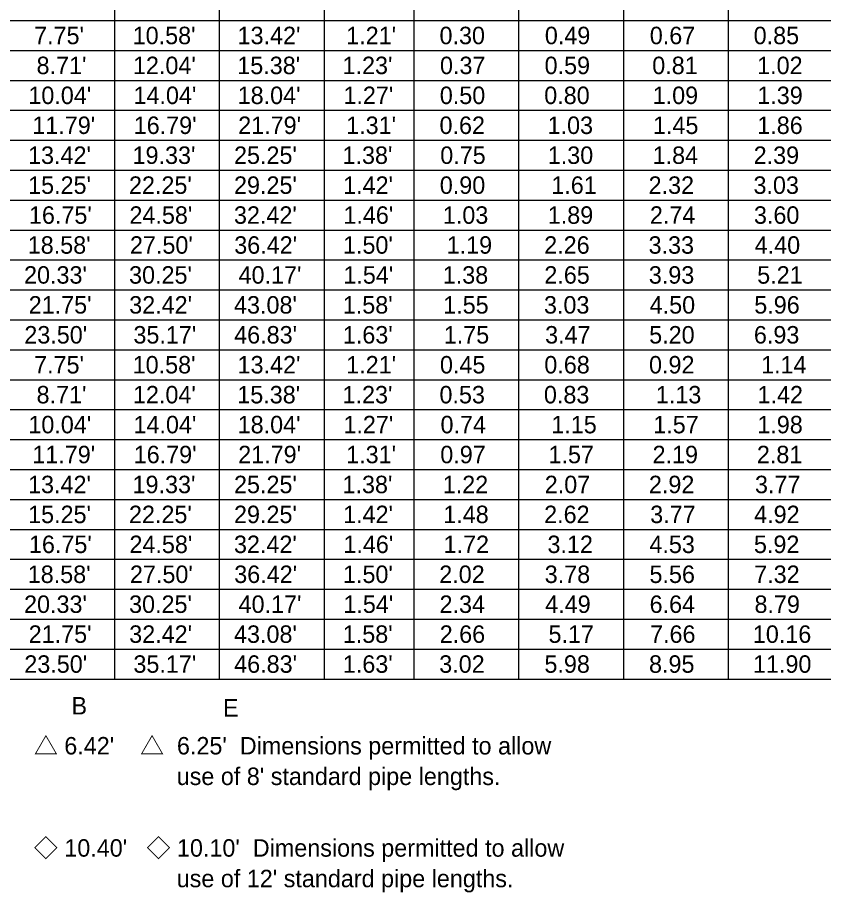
# Model space of a CAD drawing. Extents: x -1.3 to 14.6, y 0 to 8.4.
# Drawn here: x 6.831 to 10.062, y 1.334 to 4.842 of the extents above; entities that cross this region are included whole.
import ezdxf

# ---------------------------------------------------------------- set-up
doc = ezdxf.new("R2010")
doc.units = 0
doc.layers.add('Table', color=7, linetype='Continuous')

msp = doc.modelspace()

# ---------------------------------------------------------------- linework, layer by layer
at = {"layer": 'Table'}
for points in [[(7.22, 4.95), (7.22, 4.83), (7.22, 4.71), (7.22, 4.59), (7.22, 4.47), (7.22, 4.35), (7.22, 4.23), (7.22, 4.11), (7.22, 3.99), (7.22, 3.87), (7.22, 3.75), (7.22, 3.63), (7.22, 3.51), (7.22, 3.39), (7.22, 3.27), (7.22, 3.15), (7.22, 3.03), (7.22, 2.91), (7.22, 2.79), (7.22, 2.67), (7.22, 2.55), (7.22, 2.43), (7.22, 2.31), (7.22, 2.19)], [(7.64, 4.95), (7.64, 4.83), (7.64, 4.71), (7.64, 4.59), (7.64, 4.47), (7.64, 4.35), (7.64, 4.23), (7.64, 4.11), (7.64, 3.99), (7.64, 3.87), (7.64, 3.75), (7.64, 3.63), (7.64, 3.51), (7.64, 3.39), (7.64, 3.27), (7.64, 3.15), (7.64, 3.03), (7.64, 2.91), (7.64, 2.79), (7.64, 2.67), (7.64, 2.55), (7.64, 2.43), (7.64, 2.31), (7.64, 2.19)], [(8.06, 4.95), (8.06, 4.83), (8.06, 4.71), (8.06, 4.59), (8.06, 4.47), (8.06, 4.35), (8.06, 4.23), (8.06, 4.11), (8.06, 3.99), (8.06, 3.87), (8.06, 3.75), (8.06, 3.63), (8.06, 3.51), (8.06, 3.39), (8.06, 3.27), (8.06, 3.15), (8.06, 3.03), (8.06, 2.91), (8.06, 2.79), (8.06, 2.67), (8.06, 2.55), (8.06, 2.43), (8.06, 2.31), (8.06, 2.19)], [(8.42, 4.95), (8.42, 4.83), (8.42, 4.71), (8.42, 4.59), (8.42, 4.47), (8.42, 4.35), (8.42, 4.23), (8.42, 4.11), (8.42, 3.99), (8.42, 3.87), (8.42, 3.75), (8.42, 3.63), (8.42, 3.51), (8.42, 3.39), (8.42, 3.27), (8.42, 3.15), (8.42, 3.03), (8.42, 2.91), (8.42, 2.79), (8.42, 2.67), (8.42, 2.55), (8.42, 2.43), (8.42, 2.31), (8.42, 2.19)], [(8.84, 4.95), (8.84, 4.83), (8.84, 4.71), (8.84, 4.59), (8.84, 4.47), (8.84, 4.35), (8.84, 4.23), (8.84, 4.11), (8.84, 3.99), (8.84, 3.87), (8.84, 3.75), (8.84, 3.63), (8.84, 3.51), (8.84, 3.39), (8.84, 3.27), (8.84, 3.15), (8.84, 3.03), (8.84, 2.91), (8.84, 2.79), (8.84, 2.67), (8.84, 2.55), (8.84, 2.43), (8.84, 2.31), (8.84, 2.19)], [(9.26, 4.95), (9.26, 4.83), (9.26, 4.71), (9.26, 4.59), (9.26, 4.47), (9.26, 4.35), (9.26, 4.23), (9.26, 4.11), (9.26, 3.99), (9.26, 3.87), (9.26, 3.75), (9.26, 3.63), (9.26, 3.51), (9.26, 3.39), (9.26, 3.27), (9.26, 3.15), (9.26, 3.03), (9.26, 2.91), (9.26, 2.79), (9.26, 2.67), (9.26, 2.55), (9.26, 2.43), (9.26, 2.31), (9.26, 2.19)], [(9.68, 4.95), (9.68, 4.83), (9.68, 4.71), (9.68, 4.59), (9.68, 4.47), (9.68, 4.35), (9.68, 4.23), (9.68, 4.11), (9.68, 3.99), (9.68, 3.87), (9.68, 3.75), (9.68, 3.63), (9.68, 3.51), (9.68, 3.39), (9.68, 3.27), (9.68, 3.15), (9.68, 3.03), (9.68, 2.91), (9.68, 2.79), (9.68, 2.67), (9.68, 2.55), (9.68, 2.43), (9.68, 2.31), (9.68, 2.19)], [(4.04, 4.83), (4.52, 4.83), (4.94, 4.83), (5.42, 4.83), (5.66, 4.83), (6.02, 4.83), (6.38, 4.83), (6.8, 4.83), (7.22, 4.83), (7.64, 4.83), (8.06, 4.83), (8.42, 4.83), (8.84, 4.83), (9.26, 4.83), (9.68, 4.83), (10.1, 4.83), (10.52, 4.83), (10.94, 4.83), (11.36, 4.83), (11.78, 4.83), (12.2, 4.83), (12.62, 4.83), (13.04, 4.83), (13.46, 4.83)], [(4.04, 4.71), (4.52, 4.71), (4.94, 4.71), (5.42, 4.71), (5.66, 4.71), (6.02, 4.71), (6.38, 4.71), (6.8, 4.71), (7.22, 4.71), (7.64, 4.71), (8.06, 4.71), (8.42, 4.71), (8.84, 4.71), (9.26, 4.71), (9.68, 4.71), (10.1, 4.71), (10.52, 4.71), (10.94, 4.71), (11.36, 4.71), (11.78, 4.71), (12.2, 4.71), (12.62, 4.71), (13.04, 4.71), (13.46, 4.71)], [(4.04, 4.59), (4.52, 4.59), (4.94, 4.59), (5.42, 4.59), (5.66, 4.59), (6.02, 4.59), (6.38, 4.59), (6.8, 4.59), (7.22, 4.59), (7.64, 4.59), (8.06, 4.59), (8.42, 4.59), (8.84, 4.59), (9.26, 4.59), (9.68, 4.59), (10.1, 4.59), (10.52, 4.59), (10.94, 4.59), (11.36, 4.59), (11.78, 4.59), (12.2, 4.59), (12.62, 4.59), (13.04, 4.59), (13.46, 4.59)], [(4.04, 4.47), (4.52, 4.47), (4.94, 4.47), (5.42, 4.47), (5.66, 4.47), (6.02, 4.47), (6.38, 4.47), (6.8, 4.47), (7.22, 4.47), (7.64, 4.47), (8.06, 4.47), (8.42, 4.47), (8.84, 4.47), (9.26, 4.47), (9.68, 4.47), (10.1, 4.47), (10.52, 4.47), (10.94, 4.47), (11.36, 4.47), (11.78, 4.47), (12.2, 4.47), (12.62, 4.47), (13.04, 4.47), (13.46, 4.47)], [(4.04, 4.35), (4.52, 4.35), (4.94, 4.35), (5.42, 4.35), (5.66, 4.35), (6.02, 4.35), (6.38, 4.35), (6.8, 4.35), (7.22, 4.35), (7.64, 4.35), (8.06, 4.35), (8.42, 4.35), (8.84, 4.35), (9.26, 4.35), (9.68, 4.35), (10.1, 4.35), (10.52, 4.35), (10.94, 4.35), (11.36, 4.35), (11.78, 4.35), (12.2, 4.35), (12.62, 4.35), (13.04, 4.35), (13.46, 4.35)], [(4.04, 4.23), (4.52, 4.23), (4.94, 4.23), (5.42, 4.23), (5.66, 4.23), (6.02, 4.23), (6.38, 4.23), (6.8, 4.23), (7.22, 4.23), (7.64, 4.23), (8.06, 4.23), (8.42, 4.23), (8.84, 4.23), (9.26, 4.23), (9.68, 4.23), (10.1, 4.23), (10.52, 4.23), (10.94, 4.23), (11.36, 4.23), (11.78, 4.23), (12.2, 4.23), (12.62, 4.23), (13.04, 4.23), (13.46, 4.23)], [(4.04, 4.11), (4.52, 4.11), (4.94, 4.11), (5.42, 4.11), (5.66, 4.11), (6.02, 4.11), (6.38, 4.11), (6.8, 4.11), (7.22, 4.11), (7.64, 4.11), (8.06, 4.11), (8.42, 4.11), (8.84, 4.11), (9.26, 4.11), (9.68, 4.11), (10.1, 4.11), (10.52, 4.11), (10.94, 4.11), (11.36, 4.11), (11.78, 4.11), (12.2, 4.11), (12.62, 4.11), (13.04, 4.11), (13.46, 4.11)], [(4.04, 3.99), (4.52, 3.99), (4.94, 3.99), (5.42, 3.99), (5.66, 3.99), (6.02, 3.99), (6.38, 3.99), (6.8, 3.99), (7.22, 3.99), (7.64, 3.99), (8.06, 3.99), (8.42, 3.99), (8.84, 3.99), (9.26, 3.99), (9.68, 3.99), (10.1, 3.99), (10.52, 3.99), (10.94, 3.99), (11.36, 3.99), (11.78, 3.99), (12.2, 3.99), (12.62, 3.99), (13.04, 3.99), (13.46, 3.99)], [(4.04, 3.87), (4.52, 3.87), (4.94, 3.87), (5.42, 3.87), (5.66, 3.87), (6.02, 3.87), (6.38, 3.87), (6.8, 3.87), (7.22, 3.87), (7.64, 3.87), (8.06, 3.87), (8.42, 3.87), (8.84, 3.87), (9.26, 3.87), (9.68, 3.87), (10.1, 3.87), (10.52, 3.87), (10.94, 3.87), (11.36, 3.87), (11.78, 3.87), (12.2, 3.87), (12.62, 3.87), (13.04, 3.87), (13.46, 3.87)], [(4.04, 3.75), (4.52, 3.75), (4.94, 3.75), (5.42, 3.75), (5.66, 3.75), (6.02, 3.75), (6.38, 3.75), (6.8, 3.75), (7.22, 3.75), (7.64, 3.75), (8.06, 3.75), (8.42, 3.75), (8.84, 3.75), (9.26, 3.75), (9.68, 3.75), (10.1, 3.75), (10.52, 3.75), (10.94, 3.75), (11.36, 3.75), (11.78, 3.75), (12.2, 3.75), (12.62, 3.75), (13.04, 3.75), (13.46, 3.75)], [(4.04, 3.63), (4.52, 3.63), (4.94, 3.63), (5.42, 3.63), (5.66, 3.63), (6.02, 3.63), (6.38, 3.63), (6.8, 3.63), (7.22, 3.63), (7.64, 3.63), (8.06, 3.63), (8.42, 3.63), (8.84, 3.63), (9.26, 3.63), (9.68, 3.63), (10.1, 3.63), (10.52, 3.63), (10.94, 3.63), (11.36, 3.63), (11.78, 3.63), (12.2, 3.63), (12.62, 3.63), (13.04, 3.63), (13.46, 3.63)], [(4.04, 3.51), (4.52, 3.51), (4.94, 3.51), (5.42, 3.51), (5.66, 3.51), (6.02, 3.51), (6.38, 3.51), (6.8, 3.51), (7.22, 3.51), (7.64, 3.51), (8.06, 3.51), (8.42, 3.51), (8.84, 3.51), (9.26, 3.51), (9.68, 3.51), (10.1, 3.51), (10.52, 3.51), (10.94, 3.51), (11.36, 3.51), (11.78, 3.51), (12.2, 3.51), (12.62, 3.51), (13.04, 3.51), (13.46, 3.51)], [(4.04, 3.39), (4.52, 3.39), (4.94, 3.39), (5.42, 3.39), (5.66, 3.39), (6.02, 3.39), (6.38, 3.39), (6.8, 3.39), (7.22, 3.39), (7.64, 3.39), (8.06, 3.39), (8.42, 3.39), (8.84, 3.39), (9.26, 3.39), (9.68, 3.39), (10.1, 3.39), (10.52, 3.39), (10.94, 3.39), (11.36, 3.39), (11.78, 3.39), (12.2, 3.39), (12.62, 3.39), (13.04, 3.39), (13.46, 3.39)], [(4.04, 3.27), (4.52, 3.27), (4.94, 3.27), (5.42, 3.27), (5.66, 3.27), (6.02, 3.27), (6.38, 3.27), (6.8, 3.27), (7.22, 3.27), (7.64, 3.27), (8.06, 3.27), (8.42, 3.27), (8.84, 3.27), (9.26, 3.27), (9.68, 3.27), (10.1, 3.27), (10.52, 3.27), (10.94, 3.27), (11.36, 3.27), (11.78, 3.27), (12.2, 3.27), (12.62, 3.27), (13.04, 3.27), (13.46, 3.27)], [(4.04, 3.15), (4.52, 3.15), (4.94, 3.15), (5.42, 3.15), (5.66, 3.15), (6.02, 3.15), (6.38, 3.15), (6.8, 3.15), (7.22, 3.15), (7.64, 3.15), (8.06, 3.15), (8.42, 3.15), (8.84, 3.15), (9.26, 3.15), (9.68, 3.15), (10.1, 3.15), (10.52, 3.15), (10.94, 3.15), (11.36, 3.15), (11.78, 3.15), (12.2, 3.15), (12.62, 3.15), (13.04, 3.15), (13.46, 3.15)], [(4.04, 3.03), (4.52, 3.03), (4.94, 3.03), (5.42, 3.03), (5.66, 3.03), (6.02, 3.03), (6.38, 3.03), (6.8, 3.03), (7.22, 3.03), (7.64, 3.03), (8.06, 3.03), (8.42, 3.03), (8.84, 3.03), (9.26, 3.03), (9.68, 3.03), (10.1, 3.03), (10.52, 3.03), (10.94, 3.03), (11.36, 3.03), (11.78, 3.03), (12.2, 3.03), (12.62, 3.03), (13.04, 3.03), (13.46, 3.03)], [(4.04, 2.91), (4.52, 2.91), (4.94, 2.91), (5.42, 2.91), (5.66, 2.91), (6.02, 2.91), (6.38, 2.91), (6.8, 2.91), (7.22, 2.91), (7.64, 2.91), (8.06, 2.91), (8.42, 2.91), (8.84, 2.91), (9.26, 2.91), (9.68, 2.91), (10.1, 2.91), (10.52, 2.91), (10.94, 2.91), (11.36, 2.91), (11.78, 2.91), (12.2, 2.91), (12.62, 2.91), (13.04, 2.91), (13.46, 2.91)], [(4.04, 2.79), (4.52, 2.79), (4.94, 2.79), (5.42, 2.79), (5.66, 2.79), (6.02, 2.79), (6.38, 2.79), (6.8, 2.79), (7.22, 2.79), (7.64, 2.79), (8.06, 2.79), (8.42, 2.79), (8.84, 2.79), (9.26, 2.79), (9.68, 2.79), (10.1, 2.79), (10.52, 2.79), (10.94, 2.79), (11.36, 2.79), (11.78, 2.79), (12.2, 2.79), (12.62, 2.79), (13.04, 2.79), (13.46, 2.79)], [(4.04, 2.67), (4.52, 2.67), (4.94, 2.67), (5.42, 2.67), (5.66, 2.67), (6.02, 2.67), (6.38, 2.67), (6.8, 2.67), (7.22, 2.67), (7.64, 2.67), (8.06, 2.67), (8.42, 2.67), (8.84, 2.67), (9.26, 2.67), (9.68, 2.67), (10.1, 2.67), (10.52, 2.67), (10.94, 2.67), (11.36, 2.67), (11.78, 2.67), (12.2, 2.67), (12.62, 2.67), (13.04, 2.67), (13.46, 2.67)], [(4.04, 2.55), (4.52, 2.55), (4.94, 2.55), (5.42, 2.55), (5.66, 2.55), (6.02, 2.55), (6.38, 2.55), (6.8, 2.55), (7.22, 2.55), (7.64, 2.55), (8.06, 2.55), (8.42, 2.55), (8.84, 2.55), (9.26, 2.55), (9.68, 2.55), (10.1, 2.55), (10.52, 2.55), (10.94, 2.55), (11.36, 2.55), (11.78, 2.55), (12.2, 2.55), (12.62, 2.55), (13.04, 2.55), (13.46, 2.55)], [(4.04, 2.43), (4.52, 2.43), (4.94, 2.43), (5.42, 2.43), (5.66, 2.43), (6.02, 2.43), (6.38, 2.43), (6.8, 2.43), (7.22, 2.43), (7.64, 2.43), (8.06, 2.43), (8.42, 2.43), (8.84, 2.43), (9.26, 2.43), (9.68, 2.43), (10.1, 2.43), (10.52, 2.43), (10.94, 2.43), (11.36, 2.43), (11.78, 2.43), (12.2, 2.43), (12.62, 2.43), (13.04, 2.43), (13.46, 2.43)], [(4.04, 2.31), (4.52, 2.31), (4.94, 2.31), (5.42, 2.31), (5.66, 2.31), (6.02, 2.31), (6.38, 2.31), (6.8, 2.31), (7.22, 2.31), (7.64, 2.31), (8.06, 2.31), (8.42, 2.31), (8.84, 2.31), (9.26, 2.31), (9.68, 2.31), (10.1, 2.31), (10.52, 2.31), (10.94, 2.31), (11.36, 2.31), (11.78, 2.31), (12.2, 2.31), (12.62, 2.31), (13.04, 2.31), (13.46, 2.31)], [(4.04, 2.19), (4.52, 2.19), (4.94, 2.19), (5.42, 2.19), (5.66, 2.19), (6.02, 2.19), (6.38, 2.19), (6.8, 2.19), (7.22, 2.19), (7.64, 2.19), (8.06, 2.19), (8.42, 2.19), (8.84, 2.19), (9.26, 2.19), (9.68, 2.19), (10.1, 2.19), (10.52, 2.19), (10.94, 2.19), (11.36, 2.19), (11.78, 2.19), (12.2, 2.19), (12.62, 2.19), (13.04, 2.19), (13.46, 2.19)]]:
    msp.add_lwpolyline(points, dxfattribs=at)

# ---------------------------------------------------------------- texts
for s, p in [("10.58'", (7.2927, 4.735)), ("13.42'", (7.7133, 4.735)), ("1.21'", (8.1488, 4.735)), ('0.30', (8.5229, 4.735)), ('0.49', (8.9452, 4.735)), ('0.67', (9.366, 4.735)), ('0.85', (9.7824, 4.735)), ("7.75'", (6.8975, 4.735)), ("8.71'", (6.9074, 4.615)), ("12.04'", (7.2939, 4.615)), ("15.38'", (7.7121, 4.615)), ("1.23'", (8.1342, 4.615)), ('0.37', (8.5248, 4.615)), ('0.59', (8.9442, 4.615)), ('0.81', (9.3758, 4.615)), ('1.02', (9.7964, 4.615)), ("10.04'", (6.8745, 4.495)), ("14.04'", (7.296, 4.495)), ("18.04'", (7.7137, 4.495)), ("1.27'", (8.1376, 4.495)), ('0.50', (8.5241, 4.495)), ('0.80', (8.9428, 4.495)), ('1.09', (9.3776, 4.495)), ('1.39', (9.797, 4.495)), ("11.79'", (6.8903, 4.375)), ("16.79'", (7.2969, 4.375)), ("21.79'", (7.7158, 4.375)), ("1.31'", (8.1487, 4.375)), ('0.62', (8.5229, 4.375)), ('1.03', (8.9563, 4.375)), ('1.45', (9.3787, 4.375)), ('1.86', (9.7969, 4.375)), ("13.42'", (6.8733, 4.255)), ("19.33'", (7.2923, 4.255)), ("25.25'", (7.699, 4.255)), ("1.38'", (8.134, 4.255)), ('0.75', (8.5259, 4.255)), ('1.30', (8.9569, 4.255)), ('1.84', (9.3774, 4.255)), ('2.39', (9.7825, 4.255)), ("15.25'", (6.8735, 4.135)), ("22.25'", (7.2779, 4.135)), ("29.25'", (7.699, 4.135)), ("1.42'", (8.1364, 4.135)), ('0.90', (8.5241, 4.135)), ('1.61', (8.9711, 4.135)), ('2.32', (9.3612, 4.135)), ('3.03', (9.7817, 4.135)), ("16.75'", (6.8768, 4.015)), ("24.58'", (7.2798, 4.015)), ("32.42'", (7.6988, 4.015)), ("1.46'", (8.1375, 4.015)), ('1.03', (8.5363, 4.015)), ('1.89', (8.9569, 4.015)), ('2.74', (9.3664, 4.015)), ('3.60', (9.7835, 4.015)), ("18.58'", (6.872, 3.895)), ("27.50'", (7.2818, 3.895)), ("36.42'", (7.6999, 3.895)), ("1.50'", (8.1359, 3.895)), ('1.19', (8.5516, 3.895)), ('2.26', (8.9426, 3.895)), ('3.33', (9.3611, 3.895)), ('4.40', (9.7866, 3.895)), ("20.33'", (6.8572, 3.775)), ("30.25'", (7.2783, 3.775)), ("40.17'", (7.7173, 3.775)), ("1.54'", (8.1374, 3.775)), ('1.38', (8.5359, 3.775)), ('2.65', (8.9432, 3.775)), ('3.93', (9.3622, 3.775)), ('5.21', (9.7966, 3.775)), ("21.75'", (6.8758, 3.655)), ("32.42'", (7.2788, 3.655)), ("43.08'", (7.6991, 3.655)), ("1.58'", (8.1351, 3.655)), ('1.55', (8.5377, 3.655)), ('3.03', (8.9417, 3.655)), ('4.50', (9.3656, 3.655)), ('5.96', (9.7848, 3.655)), ("23.50'", (6.8583, 3.535)), ("35.17'", (7.2957, 3.535)), ("46.83'", (7.6997, 3.535)), ("1.63'", (8.1353, 3.535)), ('1.75', (8.5399, 3.535)), ('3.47', (8.9463, 3.535)), ('5.20', (9.3635, 3.535)), ('6.93', (9.7834, 3.535)), ("7.75'", (6.8975, 3.415)), ("10.58'", (7.2927, 3.415)), ("13.42'", (7.7133, 3.415)), ("1.21'", (8.1488, 3.415)), ('0.45', (8.5247, 3.415)), ('0.68', (8.9431, 3.415)), ('0.92', (9.3629, 3.415)), ('1.14', (9.8121, 3.415)), ("8.71'", (6.9074, 3.295)), ("12.04'", (7.2939, 3.295)), ("15.38'", (7.7121, 3.295)), ("1.23'", (8.1342, 3.295)), ('0.53', (8.5228, 3.295)), ('0.83', (8.9415, 3.295)), ('1.13', (9.3903, 3.295)), ('1.42', (9.7979, 3.295)), ("10.04'", (6.8745, 3.175)), ("14.04'", (7.296, 3.175)), ("18.04'", (7.7137, 3.175)), ("1.27'", (8.1376, 3.175)), ('0.74', (8.5269, 3.175)), ('1.15', (8.9711, 3.175)), ('1.57', (9.3799, 3.175)), ('1.98', (9.7971, 3.175)), ("11.79'", (6.8903, 3.055)), ("16.79'", (7.2969, 3.055)), ("21.79'", (7.7158, 3.055)), ("1.31'", (8.1487, 3.055)), ('0.97', (8.526, 3.055)), ('1.57', (8.9599, 3.055)), ('2.19', (9.3771, 3.055)), ('2.81', (9.7953, 3.055)), ("13.42'", (6.8733, 2.935)), ("19.33'", (7.2923, 2.935)), ("25.25'", (7.699, 2.935)), ("1.38'", (8.134, 2.935)), ('1.22', (8.5358, 2.935)), ('2.07', (8.9449, 2.935)), ('2.92', (9.3624, 2.935)), ('3.77', (9.7876, 2.935)), ("15.25'", (6.8735, 2.815)), ("22.25'", (7.2779, 2.815)), ("29.25'", (7.699, 2.815)), ("1.42'", (8.1364, 2.815)), ('1.48', (8.538, 2.815)), ('2.62', (8.9424, 2.815)), ('3.77', (9.3676, 2.815)), ('4.92', (9.7845, 2.815)), ("16.75'", (6.8768, 2.695)), ("24.58'", (7.2798, 2.695)), ("32.42'", (7.6988, 2.695)), ("1.46'", (8.1375, 2.695)), ('1.72', (8.5392, 2.695)), ('3.12', (8.9558, 2.695)), ('4.53', (9.3644, 2.695)), ('5.92', (9.7835, 2.695)), ("18.58'", (6.872, 2.575)), ("27.50'", (7.2818, 2.575)), ("36.42'", (7.6999, 2.575)), ("1.50'", (8.1359, 2.575)), ('2.02', (8.5219, 2.575)), ('3.78', (8.9447, 2.575)), ('5.56', (9.3647, 2.575)), ('7.32', (9.7846, 2.575)), ("20.33'", (6.8572, 2.455)), ("30.25'", (7.2783, 2.455)), ("40.17'", (7.7173, 2.455)), ('2.34', (8.523, 2.455)), ('4.49', (8.9468, 2.455)), ('6.64', (9.3652, 2.455)), ('8.79', (9.7857, 2.455)), ("1.54'", (8.1374, 2.455)), ("21.75'", (6.8758, 2.335)), ("32.42'", (7.2788, 2.335)), ("43.08'", (7.6991, 2.335)), ("1.58'", (8.1351, 2.335)), ('2.66', (8.5237, 2.335)), ('5.17', (8.9599, 2.335)), ('7.66', (9.367, 2.335)), ('10.16', (9.7792, 2.335)), ("23.50'", (6.8583, 2.215)), ("35.17'", (7.2957, 2.215)), ("46.83'", (7.6997, 2.215)), ("1.63'", (8.1353, 2.215)), ('3.02', (8.5218, 2.215)), ('5.98', (8.9436, 2.215)), ('8.95', (9.3629, 2.215)), ('11.90', (9.7797, 2.215)), ("△ 6.42'    △  6.25'  Dimensions permitted to allow ", (6.8971, 1.8875)), ("                      use of 8' standard pipe lengths.", (6.8971, 1.765)), ("◇ 10.40'   ◇ 10.10'  Dimensions permitted to allow ", (6.8971, 1.4778)), ("                      use of 12' standard pipe lengths.   ", (6.8971, 1.3553))]:
    msp.add_text(s, height=0.07, rotation=0, dxfattribs=at).set_placement(p)
for s, p in [('B', (7.0474, 2.048)), ('E', (7.6548, 2.0397))]:
    msp.add_text(s, height=0.07, dxfattribs=at).set_placement(p)

doc.saveas('drawing.dxf')
